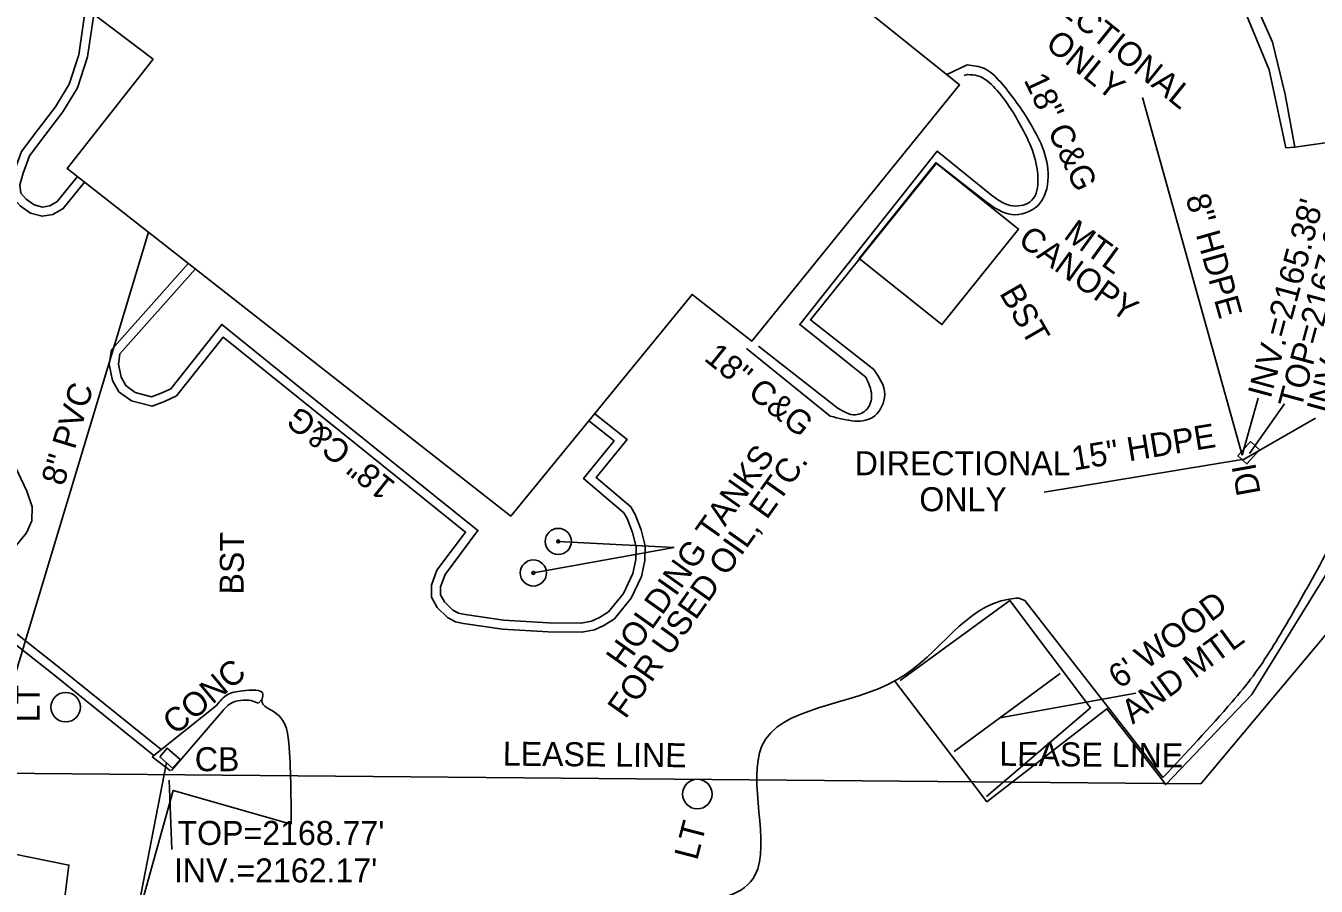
# Model space of a CAD drawing. Extents: x 945964 to 948456, y 631061 to 636061.
# Drawn here: x 947132.7 to 947347.7, y 633040.2 to 633183.5 of the extents above; entities that cross this region are included whole.
import ezdxf

# ---------------------------------------------------------------- set-up
doc = ezdxf.new("R2010")
doc.units = 0
for name, color, linetype in [('Exist Building', 7, 'Continuous'), ('Exist Building Metal Canopy', 7, 'Continuous'), ('Exist Building Metal Canopy Text', 7, 'Continuous'), ('Exist Other Culture Fence Line', 7, 'Continuous'), ('Exist Other Culture Fence Line Leader', 7, 'Continuous'), ('Exist Other Culture Fence Line Text', 7, 'Continuous'), ('Exist Other Culture Located Object CELL', 7, 'Continuous'), ('Exist Other Culture Located Object Leader', 7, 'Continuous'), ('Exist Other Culture Located Object Text', 7, 'Continuous'), ('Exist Property Line', 7, 'Continuous'), ('Exist Property Line Text', 7, 'Continuous'), ('Exist Roads Curbs', 7, 'Continuous'), ('Exist Roads Curbs Text', 7, 'Continuous'), ('Exist Roads EOP', 7, 'Continuous'), ('Exist Roads EOP Other', 7, 'Continuous'), ('Exist Roads EOP Other Text', 7, 'Continuous'), ('Exist Roads EOP Text', 7, 'Continuous'), ('Exist Roads Soil', 7, 'Continuous'), ('Exist Structure Minor Catch Basin', 7, 'Continuous'), ('Exist Structure Minor Catch Basin Text', 7, 'Continuous'), ('Exist Structure Minor Catch Basin Top Elevation', 7, 'Continuous'), ('Exist Structure Minor Culvert Topo Leader', 7, 'Continuous'), ('Exist Structure Minor Drop Inlet', 7, 'Continuous'), ('Exist Structure Minor Drop Inlet Text', 7, 'Continuous'), ('Exist Structure Minor Pipes HDPE 15 Inch', 7, 'Continuous'), ('Exist Structure Minor Pipes HDPE 15 Inch Invert', 7, 'Continuous'), ('Exist Structure Minor Pipes HDPE 15 Inch Text', 7, 'Continuous'), ('Exist Structure Minor Pipes HDPE 24 Inch', 7, 'Continuous'), ('Exist Structure Minor Pipes HDPE 24 Inch Invert', 7, 'Continuous'), ('Exist Structure Minor Pipes HDPE 24 Inch Leader', 7, 'Continuous'), ('Exist Structure Minor Pipes HDPE 8 Inch', 7, 'Continuous'), ('Exist Structure Minor Pipes HDPE 8 Inch Invert', 7, 'Continuous'), ('Exist Structure Minor Pipes HDPE 8 Inch Leader', 7, 'Continuous'), ('Exist Structure Minor Pipes HDPE 8 Inch Text', 7, 'Continuous'), ('Exist Utilities Other Pole CELL', 7, 'Continuous'), ('Exist Utilities Other Pole Text', 7, 'Continuous'), ('Exist Utilities Sanitary Sewer UG Line', 7, 'Continuous'), ('Exist Utilities Sanitary Sewer UG Line Text', 7, 'Continuous')]:
    doc.layers.add(name, color=color, linetype=linetype)

msp = doc.modelspace()

# ---------------------------------------------------------------- linework, layer by layer
at = {"layer": 'Exist Building'}
msp.add_lwpolyline([(947213.57, 633101.79), (947139.61, 633159.75), (947153.96, 633177.93), (947112.43, 633209.39), (947140.47, 633243.87), (947134.27, 633248.53), (947144.16, 633263.17), (947125.73, 633277.87), (947148.29, 633306.13), (947165.45, 633292.19), (947178.78, 633305.02), (947185, 633300.14), (947191.52, 633307.66), (947246.07, 633263.8), (947235.21, 633249.84), (947263.76, 633226.47), (947247.76, 633206.2), (947288.32, 633173.67), (947253.69, 633130.99), (947243.76, 633138.75)], close=True, dxfattribs=at)
at = {"layer": 'Exist Building Metal Canopy'}
msp.add_lwpolyline([(947271.6, 633144.77), (947285.39, 633133.73), (947298.14, 633149.65), (947284.35, 633160.7)], close=True, dxfattribs=at)
at = {"layer": 'Exist Other Culture Fence Line'}
msp.add_line((947287.43, 633062.63), (947305.1, 633075.63), dxfattribs=at)
at = {"layer": 'Exist Other Culture Fence Line Leader'}
msp.add_line((947295.02, 633068.21), (947317.69, 633072.33), dxfattribs=at)
at = {"layer": 'Exist Other Culture Located Object CELL'}
for centre, radius in [((947221.46, 633097.61), 2.18), ((947221.46, 633097.61), 0.24), ((947217.31, 633092.36), 2.18), ((947217.31, 633092.36), 0.24)]:
    msp.add_circle(centre, radius, dxfattribs=at)
at = {"layer": 'Exist Other Culture Located Object Leader'}
for p in [(947221.46, 633097.61), (947217.31, 633092.36)]:
    msp.add_line(p, (947240.78, 633096.62), dxfattribs=at)
at = {"layer": 'Exist Property Line'}
for p, q in [((947328.55, 633057.21), (947392.75, 633134.07)), ((947118.56, 633059.11), (947328.55, 633057.21))]:
    msp.add_line(p, q, dxfattribs=at)
at = {"layer": 'Exist Roads Curbs'}
for p, q in [((947289.67, 633175.38), (947289.11, 633175.22)), ((947254.81, 633130.13), (947268.1, 633119.77)), ((947171.5, 633070.66), (947170.24, 633071.12)), ((947171.5, 633070.66), (947172.07, 633071.29)), ((947165.5, 633069.35), (947157.04, 633059.46))]:
    msp.add_line(p, q, dxfattribs=at)
for points in [[(947251.32, 633284.27), (947264.5, 633269.48), (947272.58, 633260.03), (947280.12, 633246.31), (947289.88, 633227.37), (947296.09, 633215.15), (947297.46, 633212.86), (947299.01, 633211.34), (947301.16, 633210.78), (947303.31, 633211.19), (947304.45, 633212.72), (947310.58, 633219.87), (947317.87, 633212.76), (947325.85, 633204.36), (947331.9, 633197.35), (947336.46, 633189.85), (947340.47, 633180.78), (947342.6, 633172.09), (947344.18, 633163.29)], [(947141.35, 633158.39), (947137.98, 633154.24), (947136.74, 633153.53), (947135.52, 633153.31), (947134.15, 633153.68), (947132.81, 633154.61), (947131.94, 633155.63), (947131.73, 633157.03), (947132.29, 633158.95), (947133.35, 633161.87), (947135.91, 633165.26), (947138.92, 633169.15), (947141.34, 633173.16), (947143.05, 633178.34), (947144.08, 633185.41)], [(947272.7, 633124.97), (947261.69, 633133.74), (947284.6, 633162.63), (947293.63, 633155.3)], [(947160.99, 633143), (947148.42, 633128.86), (947148.18, 633127.12), (947148.61, 633124.95), (947149.4, 633123.57), (947150.99, 633122.4), (947153.7, 633121.71), (947155.3, 633122.29), (947156.89, 633123.05), (947165.38, 633133.75), (947179.04, 633122.75), (947208.08, 633099.43), (947202.59, 633092.11), (947201.84, 633090.05), (947201.85, 633088.71), (947202.5, 633087.52), (947203.9, 633086.16), (947204.85, 633085.66), (947205.96, 633085.41), (947212.31, 633084.5), (947219.81, 633084.03), (947225.26, 633083.98), (947227.01, 633084.3), (947228.33, 633084.94), (947229.82, 633085.86), (947232.31, 633088.95), (947233.9, 633092.24), (947234.37, 633094.61), (947234.43, 633096.69), (947233.84, 633099.1), (947232.92, 633101.45), (947232.39, 633102.37), (947225.68, 633108.1), (947230.8, 633114.35), (947226.58, 633117.72)], [(947121.74, 633087.74), (947137.3, 633075.51), (947154.1, 633061.96)]]:
    msp.add_lwpolyline(points, dxfattribs=at)
for points in [[(947293.63, 633155.3), (947297.24, 633153.5), (947300.38, 633154.46), (947301.38, 633158.03), (947298.44, 633167.02), (947294.28, 633173.06), (947291.33, 633175.18), (947289.67, 633175.38)], [(947268.1, 633119.77), (947270.98, 633118.71), (947272.91, 633119.65), (947273.66, 633121.99), (947272.7, 633124.97)], [(947170.24, 633071.12), (947168.96, 633071.16), (947167.16, 633070.76), (947165.5, 633069.35)]]:
    msp.add_spline(points, degree=3, dxfattribs=at)
at = {"layer": 'Exist Roads EOP'}
for p, q in [((947289.58, 633176.99), (947286.2, 633175.37)), ((947289.58, 633176.99), (947288.9, 633176.66)), ((947252.83, 633129.75), (947266.78, 633118.5)), ((947299.2, 633087.75), (947298.18, 633088.17)), ((947322.22, 633058.27), (947299.2, 633087.75)), ((947164.5, 633070.3), (947153.79, 633061.71))]:
    msp.add_line(p, q, dxfattribs=at)
for points in [[(947142.53, 633157.47), (947138.97, 633153.07), (947137.26, 633152.1), (947135.45, 633151.77), (947133.5, 633152.3), (947131.79, 633153.49), (947130.52, 633154.98), (947130.2, 633157.13), (947130.86, 633159.42), (947132.01, 633162.59), (947134.72, 633166.18), (947137.68, 633170), (947139.97, 633173.79), (947141.59, 633178.69), (947142.71, 633186.45)], [(947094.12, 633166.48), (947098.78, 633161.07), (947103.57, 633155.26), (947109.16, 633147.65), (947114.97, 633139.44), (947119.99, 633131.11), (947124.42, 633123.31), (947128.74, 633114.81), (947132.91, 633105.98), (947133.82, 633103.39), (947133.73, 633101.06), (947132.85, 633099.03), (947123.87, 633087.97), (947138.23, 633076.68), (947155.3, 633062.92)], [(947274.02, 633126.25), (947263.47, 633134.5), (947284.49, 633160.62), (947292.77, 633154.21)], [(947284.48, 633160.6), (947284.49, 633160.62), (947292.77, 633154.21)], [(947159.8, 633143.93), (947147, 633129.51), (947146.66, 633127.07), (947147.18, 633124.42), (947148.26, 633122.55), (947150.33, 633121.02), (947153.78, 633120.14), (947155.88, 633120.9), (947157.84, 633121.84), (947165.62, 633131.63), (947178.1, 633121.58), (947206.01, 633099.17), (947201.25, 633092.83), (947200.34, 633090.31), (947200.35, 633088.32), (947201.29, 633086.6), (947203, 633084.94), (947204.33, 633084.23), (947205.69, 633083.94), (947212.15, 633083.01), (947219.76, 633082.53), (947225.39, 633082.48), (947227.48, 633082.86), (947229.05, 633083.62), (947230.83, 633084.72), (947233.59, 633088.14), (947235.33, 633091.76), (947235.87, 633094.44), (947235.94, 633096.85), (947235.27, 633099.55), (947234.27, 633102.11), (947233.56, 633103.35), (947227.77, 633108.28), (947232.93, 633114.58), (947227.53, 633118.88)], [(947113.88, 632943.28), (947128.25, 632943.31), (947134.74, 632974.95), (947142.42, 633001.31), (947148.64, 633024.57), (947146.33, 633025.66), (947143.49, 633026.52), (947123.04, 633031.03), (947124.32, 633046.82), (947139.93, 633043.7), (947139, 633036.57), (947147.97, 633033.97), (947150.97, 633033.43), (947157.32, 633056.12), (947176.95, 633050.49)]]:
    msp.add_lwpolyline(points, dxfattribs=at)
for points in [[(947292.77, 633154.21), (947297, 633152.06), (947301.34, 633153.54), (947303.08, 633158.35), (947299.83, 633167.71), (947295.07, 633174.21), (947292.49, 633176.39), (947289.58, 633176.99)], [(947292.77, 633154.21), (947297, 633152.06), (947301.34, 633153.54), (947303.08, 633158.35), (947299.83, 633167.71), (947295.07, 633174.21), (947292.49, 633176.39), (947289.58, 633176.99)], [(947359.79, 633165.24), (947363.74, 633148.31), (947364.09, 633143.03), (947363.77, 633137.73), (947362.94, 633132.43), (947362.38, 633129.79), (947361.75, 633127.15), (947360.22, 633121.62), (947358.47, 633116.25), (947355.4, 633108.35), (947354.25, 633105.74), (947352.32, 633101.57), (947350.32, 633097.47), (947347.12, 633091.41), (947345.99, 633089.41), (947343.21, 633084.56), (947340.34, 633079.78), (947337.23, 633075.19), (947333.74, 633070.9), (947322.22, 633058.27)], [(947266.78, 633118.5), (947274.19, 633118.54), (947275.85, 633122.1), (947274.02, 633126.25)], [(947298.18, 633088.17), (947296.61, 633088.01), (947278.03, 633074.64), (947255.4, 633063.54), (947254.28, 633042.05), (947227.06, 633033.92), (947215.52, 633017.58), (947206.92, 632984.82), (947198.59, 632957.8), (947191.56, 632936.98), (947175.57, 632908.24), (947141.51, 632917.74), (947113.53, 632922.38)], [(947176.95, 633050.49), (947176.63, 633063.26), (947174.38, 633069.01), (947172.09, 633071.11), (947172.25, 633072.1), (947168.84, 633072.71), (947166.39, 633072.11), (947164.5, 633070.3)]]:
    msp.add_spline(points, degree=3, dxfattribs=at)
at = {"layer": 'Exist Roads EOP Other'}
for points in [[(947344.18, 633163.29), (947342.71, 633163.18), (947339.91, 633176.19), (947334.59, 633189.09), (947330.42, 633196.08), (947325.99, 633201.8), (947319.39, 633208.75), (947310.5, 633217.95), (947303.35, 633210.08), (947301.74, 633209.17), (947298.95, 633209.52), (947296.79, 633211.27), (947293.78, 633216.86), (947286.78, 633230.46), (947275.34, 633251.9), (947270.84, 633259.41), (947266.11, 633265.69), (947254.14, 633278.96)], [(947344.18, 633163.29), (947349.26, 633164.03), (947359.79, 633165.24)], [(947278.44, 633074.45), (947296.7, 633087.77), (947310.15, 633069.91), (947292.84, 633055.12)]]:
    msp.add_lwpolyline(points, dxfattribs=at)
at = {"layer": 'Exist Roads Soil'}
for points in [[(947166.57, 632907.62), (947205.68, 632892), (947298.82, 632887.32), (947341.89, 632916.95), (947380.3, 632952.96), (947399.54, 633012.2), (947394.55, 633034.88), (947389.03, 633069.7), (947351.39, 633095.4), (947337.03, 633072.12)], [(947337.03, 633072.12), (947322.69, 633057.11), (947312.87, 633069.74), (947292.87, 633054.25), (947277.55, 633074.34)]]:
    msp.add_lwpolyline(points, dxfattribs=at)
at = {"layer": 'Exist Structure Minor Catch Basin'}
msp.add_line((947153.79, 633061.71), (947156.86, 633059.41), dxfattribs=at)
msp.add_lwpolyline([(947155.05, 633061.72), (947157.21, 633059.86), (947158.44, 633061.29), (947156.27, 633063.15)], close=True, dxfattribs=at)
at = {"layer": 'Exist Structure Minor Culvert Topo Leader'}
msp.add_line((947336.66, 633112.23), (947342.44, 633120.51), dxfattribs=at)
at = {"layer": 'Exist Structure Minor Drop Inlet'}
msp.add_lwpolyline([(947338.32, 633112.89), (947336.81, 633114.23), (947334.71, 633111.87), (947336.21, 633110.53)], close=True, dxfattribs=at)
at = {"layer": 'Exist Structure Minor Pipes HDPE 15 Inch'}
msp.add_line((947335.73, 633111.32), (947302.41, 633105.81), dxfattribs=at)
at = {"layer": 'Exist Structure Minor Pipes HDPE 15 Inch Invert'}
msp.add_line((947335.73, 633111.32), (947347.61, 633118.17), dxfattribs=at)
at = {"layer": 'Exist Structure Minor Pipes HDPE 24 Inch'}
msp.add_line((947120.08, 632876.58), (947156.21, 633060.77), dxfattribs=at)
at = {"layer": 'Exist Structure Minor Pipes HDPE 24 Inch Leader'}
msp.add_line((947156.61, 633057.85), (947157.07, 633046.28), dxfattribs=at)
at = {"layer": 'Exist Structure Minor Pipes HDPE 8 Inch'}
msp.add_line((947335.43, 633111.99), (947318.82, 633171.57), dxfattribs=at)
at = {"layer": 'Exist Structure Minor Pipes HDPE 8 Inch Leader'}
msp.add_line((947335.43, 633111.99), (947338.09, 633121.48), dxfattribs=at)
at = {"layer": 'Exist Utilities Other Pole CELL'}
for centre in [(947139.38, 633070), (947244.63, 633055.52)]:
    msp.add_circle(centre, 2.46, dxfattribs=at)
at = {"layer": 'Exist Utilities Sanitary Sewer UG Line'}
msp.add_lwpolyline([(947066.74, 633008.31), (947120.81, 633041.82), (947153.16, 633149.12)], dxfattribs=at)

# ---------------------------------------------------------------- texts
at = {"layer": 'Exist Building Metal Canopy Text'}
for s, p in [('MTL', (947305.48, 633148.25)), ('CANOPY', (947297.86, 633147.28))]:
    msp.add_text(s, height=4, rotation=324.0928, dxfattribs=at).set_placement(p)
at = {"layer": 'Exist Other Culture Fence Line Text'}
for s, p in [("6' WOOD", (947315.01, 633072.92)), ('AND MTL', (947317.17, 633067.06))]:
    msp.add_text(s, height=4, rotation=36.3416, dxfattribs=at).set_placement(p)
at = {"layer": 'Exist Other Culture Located Object Text'}
for s, p in [('HOLDING TANKS', (947232.41, 633076.19)), ('FOR USED OIL, ETC.', (947232.66, 633067.88))]:
    msp.add_text(s, height=4, rotation=54.6764, dxfattribs=at).set_placement(p)
at = {"layer": 'Exist Property Line Text'}
for p in [(947212.21, 633060.26), (947294.94, 633060.24)]:
    msp.add_text('LEASE LINE', height=4, rotation=359.4791, dxfattribs=at).set_placement(p)
at = {"layer": 'Exist Roads Curbs Text'}
msp.add_text('CONC', height=4, rotation=39.7799, dxfattribs=at).set_placement((947157.65, 633065.22))
at = {"layer": 'Exist Roads EOP Other Text'}
for rotation, p in [(300.0227, (947294.88, 633138.97)), (89.3313, (947169.01, 633088.75))]:
    msp.add_text('BST', height=4, rotation=rotation, dxfattribs=at).set_placement(p)
at = {"layer": 'Exist Roads EOP Text'}
for rotation, p in [(295.063, (947298.97, 633174.51)), (321.1121, (947245.58, 633127.89)), (141.2394, (947194.56, 633107.28))]:
    msp.add_text('18" C&G', height=4, rotation=rotation, dxfattribs=at).set_placement(p)
at = {"layer": 'Exist Structure Minor Catch Basin Text'}
msp.add_text('CB', height=4, dxfattribs=at).set_placement((947160.9, 633059.33))
at = {"layer": 'Exist Structure Minor Catch Basin Top Elevation'}
msp.add_text("TOP=2167.61'", height=4, rotation=74.8676, dxfattribs=at).set_placement((947345.22, 633119.53))
msp.add_text("TOP=2168.77'", height=4, dxfattribs=at).set_placement((947158.02, 633047.04))
at = {"layer": 'Exist Structure Minor Drop Inlet Text'}
msp.add_text('DI', height=4, rotation=100.2443, dxfattribs=at).set_placement((947338.51, 633105.62))
at = {"layer": 'Exist Structure Minor Pipes HDPE 15 Inch Invert'}
msp.add_text("INV.=2164.23'", height=4, rotation=74.8676, dxfattribs=at).set_placement((947349.94, 633118.71))
for s, p in [('DIRECTIONAL', (947270.85, 633108.64)), ('ONLY', (947281.62, 633102.64))]:
    msp.add_text(s, height=4, dxfattribs=at).set_placement(p)
at = {"layer": 'Exist Structure Minor Pipes HDPE 15 Inch Text'}
for height, p in [(4, (947307.34, 633109.41)), (1.5000000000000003e-11, (947332.22, 633111.5))]:
    msp.add_text('15" HDPE', height=height, rotation=9.3911, dxfattribs=at).set_placement(p)
at = {"layer": 'Exist Structure Minor Pipes HDPE 24 Inch Invert'}
msp.add_text("INV.=2162.17'", height=4, dxfattribs=at).set_placement((947157.42, 633040.8))
at = {"layer": 'Exist Structure Minor Pipes HDPE 8 Inch Invert'}
msp.add_text("INV.=2165.38'", height=4, rotation=74.8676, dxfattribs=at).set_placement((947340.15, 633121.27))
at = {"layer": 'Exist Structure Minor Pipes HDPE 8 Inch Text'}
for s, height, rotation, p in [('DRECTIONAL', 4, 321.0794, (947298.33, 633191.08)), ('ONLY', 4, 321.0794, (947302.42, 633180.06)), ('8" HDPE', 4, 285.5824, (947325.96, 633154.91)), ('8" HDPE', 1.5000000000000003e-11, 285.5824, (947334.63, 633113.4))]:
    msp.add_text(s, height=height, rotation=rotation, dxfattribs=at).set_placement(p)
at = {"layer": 'Exist Utilities Other Pole Text'}
for rotation, p in [(90, (947135.03, 633067.46)), (75.4496, (947244.61, 633044.34))]:
    msp.add_text('LT', height=4, rotation=rotation, dxfattribs=at).set_placement(p)
at = {"layer": 'Exist Utilities Sanitary Sewer UG Line Text'}
msp.add_text('8" PVC', height=4, rotation=73.2218, dxfattribs=at).set_placement((947139.06, 633106.69))

doc.saveas('drawing.dxf')
